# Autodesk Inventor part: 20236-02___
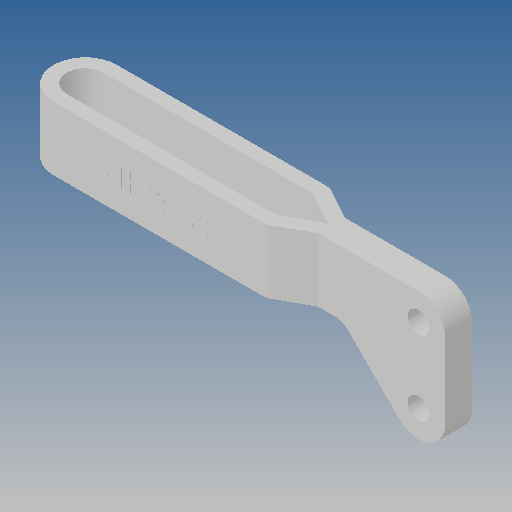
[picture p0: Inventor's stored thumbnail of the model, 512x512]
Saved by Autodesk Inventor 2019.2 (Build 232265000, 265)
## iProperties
Created: 2010-06
Part Number: 20236-02___
Material: Ogólny
Document SubType Name: Modeling
Designer: CADENGINEERING4
Density: 1 g/cm^3
Appearance: Domyślna
Author: CADENGINEERING4
Revision Number: ANY
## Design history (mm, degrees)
feature "NONE"
node "Bryła1"
